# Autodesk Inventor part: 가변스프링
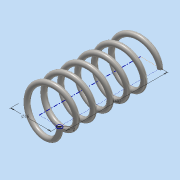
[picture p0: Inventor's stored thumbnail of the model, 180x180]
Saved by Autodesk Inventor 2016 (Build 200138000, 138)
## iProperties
Created: 2018-06
Part Number: 가변스프링
Material: 강철, 탄소
Document SubType Name: Modeling
Designer: 602-09
Density: 7.85 g/cm^3
Appearance: 반연마
Mass: 7.35983 g
Surface Area: 18.9964 cm^2
Volume: 0.937559 cm^3
Author: 602-09
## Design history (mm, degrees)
sketch "스케치1"
  geometry: L1 (0, 0)-(8, 0); L2 (8, 0)-(8, 33); L3 (8, 33)-(0, 33); L4 (0, 33)-(0, 0); C1 r 1 at (8, 0)
  constraints: 8 end point, 2 parallel, 1 centre point, 1 coincident, 1 horizontal, 1 perpendicular
  dimensions: "d0" = 2 diameter of C1; "d1" = 33 distance of L1.end L2.end (derived); "d2" = 16 diameter of L2 L4
feature "코일1" pitch "d3" = 10; turns "d5" = 6; dims "d4" = 33 (computed from d1), "d6" = 0, angle "d7" = 90 deg, angle "d8" = 90 deg, "d9" = 0, "d10" = 0
sketch "스케치2"
  geometry: L1 (-9, 0)-(-7, 0) reference; 1 further point
  constraints: 1 horizontal alignment
extrude "돌출1" cut sketch "스케치2" stored distance "d11" = 10; taper "d12" = 0 deg
node "작업 평면1"
sketch "스케치3"
  geometry: L1 (1, 0)-(-1, 0) reference; 1 further point
  constraints: 1 horizontal alignment
extrude "돌출2" cut sketch "스케치3" stored distance "d14" = 10; taper "d15" = 0 deg
node "솔리드1"
node "절단 모서리 투영1"
node "절단 모서리 투영2"
other parameters: "d13" = 90 deg
